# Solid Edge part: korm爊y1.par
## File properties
Author: morva
Template: iso metric part.par
Last saved by: morva
Revision: 23
Application: Solid Edge
Density: 2712.000 kg/m^3
Accuracy: 0.990
Username: morva
Material: Aluminum, 6061-T6
Face Style: Aluminum
Fill Style: ANSI38(Aluminum)
Virtual Style: Polished aluminum
Grouping: Metals\Aluminium Alloys
LibraryName: Materials
Coef. of Thermal Exp: 2.3e-05
Thermal Conductivity: 180.0
Specific Heat: 920.0
Modulus of Elasticity: 68947570000.0
Poisson's Ratio: 0.33
Yield Stress: 275790280.0
Ultimate Stress: 310264065.0
Elongation: 0.0
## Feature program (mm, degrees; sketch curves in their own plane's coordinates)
swept protrusion "SweptProtrusion_1"
swept protrusion "SweptProtrusion_3"
swept cutout "SweptCutout_2"
mirror "unnamed Mirror 1" of "SweptProtrusion_3"
pattern "unnamed Pattern 1"
mirror "unnamed Mirror 2" of "SweptCutout_2" about plane through (0, 0, 0) normal (1, 0, 0)
swept cutout "unnamed SweptCutout 1"
swept cutout "SweptCutout_1"
sketch for "unnamed Cutout 1" plane through (0, 0, 0) normal (0, -1, 0) x-axis (1, 0, 0)
  circle centre (-60, 0) radius 5
extrude "unnamed Cutout 1" cut through along -normal
mirror "unnamed Mirror 3" of "unnamed Cutout 1"
pattern "unnamed Pattern 2"
chamfer "Chamfer_1" setback 1
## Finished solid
Body 1: solid body, 20 faces, 38 edges, 20 vertices.
  Faces by surface: cylinder 16, plane 3, cone 1
  Edges by curve: ellipse 21, intersection 10, circle 7
Bounding box of the edges (mm): 553.820 x 47.880 x 481.714, from (-276.9101, -36.8801, -470.7144) to (276.9101, 11, 11).
Cylindrical faces by radius (mm): R5 x2, R9 x6, R11 x8
Conical faces (half-angle, radius in mm at the cone's reference point): 45 deg R10 x1
Planar faces by outward normal: -z 1, oblique 2
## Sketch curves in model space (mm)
circle centre (0, 0, -200) radius 9
circle centre (0, 0, -200) radius 11
line (0, 0, -70.7144) -> (0, 0, -470.7144)
line (-70.707, 0, 0) -> (0, 0, -70.7144)
circle centre (0, 0, 0) radius 11
circle centre (0, 0, 0) radius 9
line (127.2788, 0, 0) -> (275, -26.0472, 0)
line (-127.2788, 0, 0) -> (127.2788, 0, 0)
line (-275, -26.0472, 0) -> (-127.2788, 0, 0)
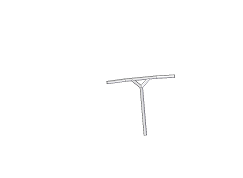
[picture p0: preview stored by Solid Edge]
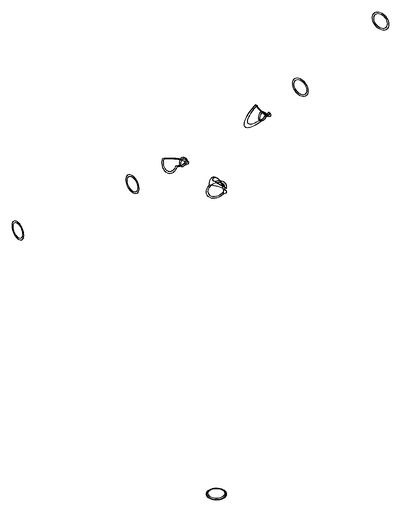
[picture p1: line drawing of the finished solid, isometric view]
